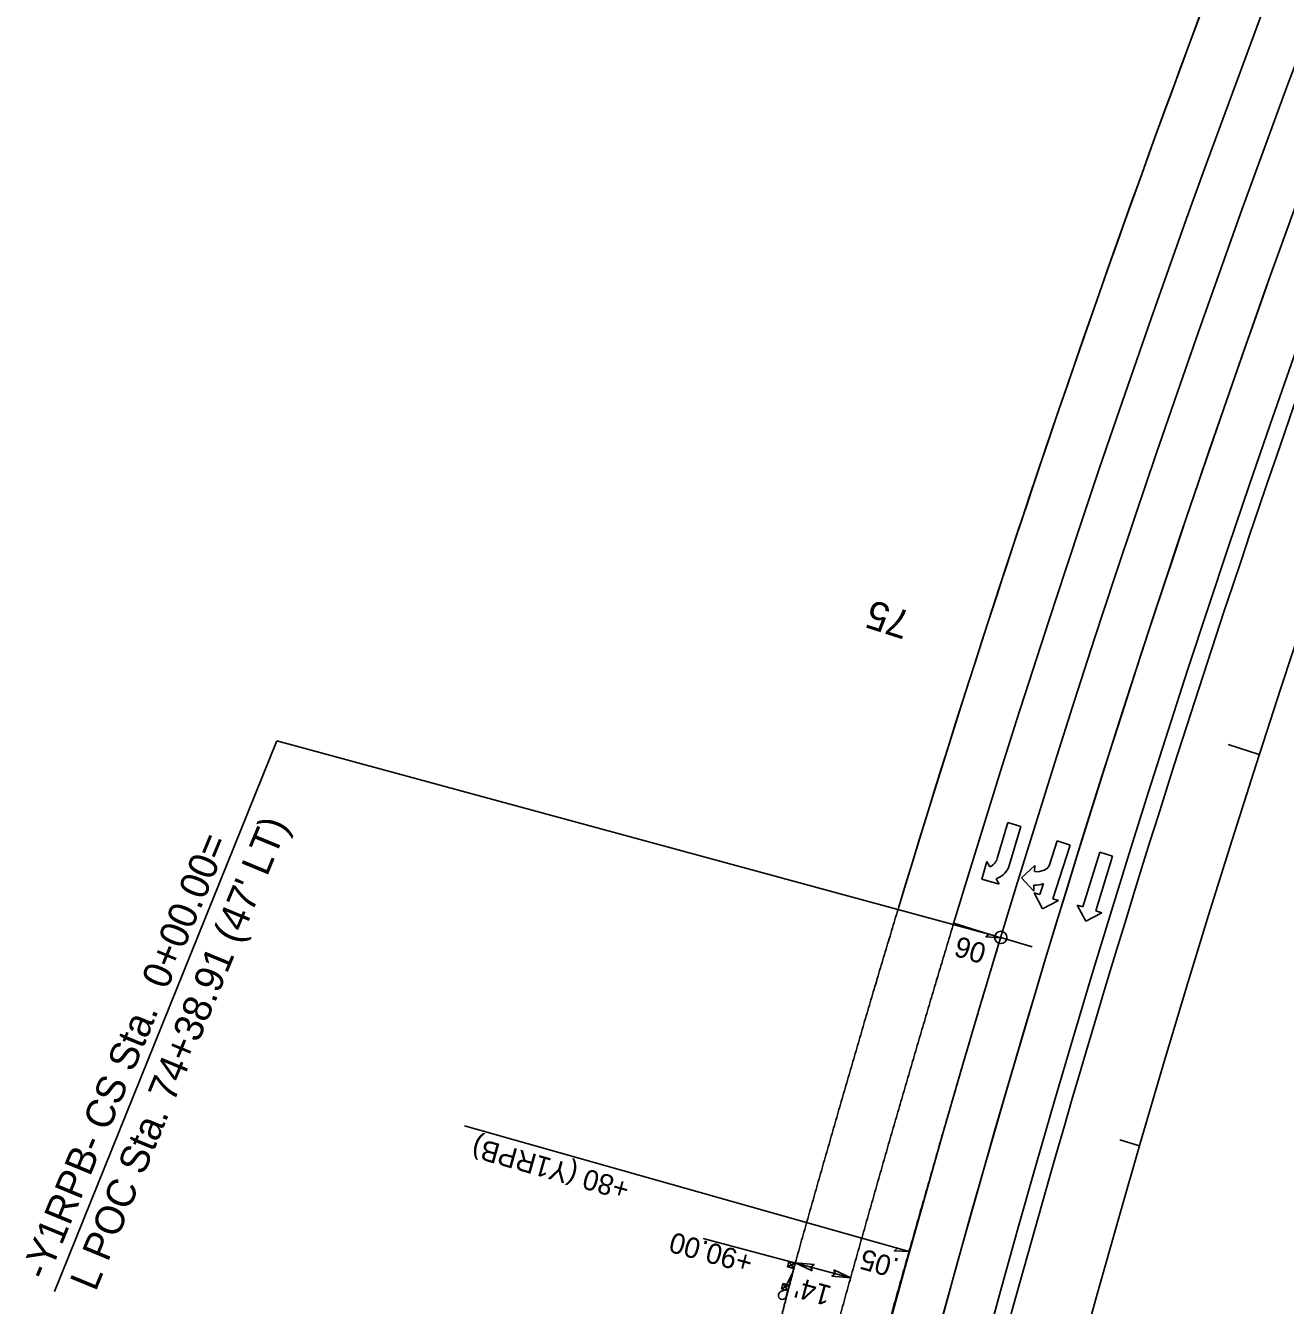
# Model space of a CAD drawing. Extents: x 2389694 to 2405615, y 547005 to 573532.
# Drawn here: x 2395096.3 to 2395404.2, y 556416.9 to 556729.7 of the extents above; entities that cross this region are included whole.
import ezdxf

# ---------------------------------------------------------------- set-up
doc = ezdxf.new("R2010")
doc.units = 0
for name, color, linetype in [('Old_Level_1', 7, 'Continuous'), ('Old_Level_22', 7, 'Continuous'), ('Prop Dimension', 7, 'Continuous'), ('Prop Dimension Text', 7, 'Continuous'), ('Prop EOT', 7, 'Continuous'), ('Prop GRAU CAT1 CELL', 7, 'Continuous'), ('Prop Guardrail', 7, 'Continuous'), ('Prop Horizontal Alignment', 7, 'Continuous'), ('Prop Horizontal Alignment Curve and Spiral Data', 7, 'Continuous'), ('Prop Horizontal Alignment Tick Large', 7, 'Continuous'), ('Prop Horizontal Alignment Tick Small', 7, 'Continuous'), ('Prop Lane Arrow Shared Rt and Thru CELL', 7, 'Continuous'), ('Prop Lane Arrow Through CELL', 7, 'Continuous'), ('Prop Lane Lines', 7, 'Continuous'), ('Prop Super Arrow 1 Lane CELL', 7, 'Continuous'), ('Prop Superelevation Label', 7, 'Continuous')]:
    doc.layers.add(name, color=color, linetype=linetype)

# ---------------------------------------------------------------- blocks, each defined once
blk = doc.blocks.new('CAT1 GRAU')
at = {"layer": 'Prop GRAU CAT1 CELL'}
for p, q in [((-0.02, -0.02), (6.71, -0.02)), ((-0.02, -0.02), (1.38, -0.02)), ((-0.02, -1.63), (-0.02, -0.02)), ((-0.02, -0.02), (1.38, -1.63)), ((1.38, -0.02), (-0.02, -1.63)), ((1.38, -1.63), (-0.02, -1.63)), ((1.38, -0.02), (1.38, -1.63)), ((6.27, -0.83), (2.47, -0.02)), ((5.57, -0.02), (6.97, -0.02)), ((5.57, -1.63), (5.57, -0.02)), ((5.57, -0.02), (6.97, -1.63)), ((6.97, -0.02), (5.57, -1.63)), ((6.97, -1.63), (5.57, -1.63)), ((6.71, -0.02), (6.44, -0.02)), ((6.71, -0.02), (8.42, -0.02)), ((6.97, -0.02), (6.97, -1.63)), ((7.63, -1.6), (6.97, -0.72))]:
    blk.add_line(p, q, dxfattribs=at)
blk.add_ellipse((8.42, -1.01), major_axis=(0, 0.993), ratio=0.995379, start_param=2.210226, end_param=6.283185, dxfattribs=at)

msp = doc.modelspace()

# ---------------------------------------------------------------- linework, layer by layer
at = {"layer": 'Prop Dimension'}
for p, q in [((2395300.65, 556433.28), (2395203.53, 556460.73)), ((2395297.94, 556423.62), (2395261.86, 556433.2))]:
    msp.add_line(p, q, dxfattribs=at)
for points in [[(2395288.55, 556425.32), (2395284.4, 556427.22), (2395288.98, 556426.83), (2395288.21, 556426.21)], [(2395293.78, 556425.53), (2395297.94, 556423.62), (2395293.36, 556424.01), (2395294.12, 556424.64)]]:
    msp.add_lwpolyline(points, close=True, dxfattribs=at)
at = {"layer": 'Prop EOT'}
for radius, start, end in [(3559, 136.54853, 163.17888), (3523, 136.54853, 169.40696), (3573, 151.19964, 163.17888), (3519, 155.66284, 169.40696)]:
    msp.add_arc((2398729.82, 555480.32), radius, start, end, dxfattribs=at)
for points in [[(2395309.71, 556514.32), (2395308.92, 556511.73), (2395308.14, 556509.12), (2395307.36, 556506.51), (2395306.57, 556503.91), (2395305.8, 556501.3), (2395305.02, 556498.69), (2395304.24, 556496.08), (2395303.47, 556493.48), (2395302.7, 556490.87), (2395301.93, 556488.26), (2395301.16, 556485.65), (2395300.4, 556483.04), (2395299.63, 556480.43), (2395298.87, 556477.82), (2395298.11, 556475.21), (2395297.35, 556472.6), (2395296.59, 556469.99), (2395295.84, 556467.38), (2395295.08, 556464.77), (2395294.33, 556462.16), (2395293.58, 556459.55), (2395292.83, 556456.94), (2395292.08, 556454.32), (2395291.33, 556451.71), (2395290.59, 556449.1), (2395289.84, 556446.49), (2395289.1, 556443.88), (2395288.36, 556441.26), (2395287.62, 556438.65), (2395286.88, 556436.04), (2395286.14, 556433.43), (2395285.41, 556430.81), (2395284.67, 556428.2), (2395284.38, 556427.17)], [(2395268.75, 556317.47), (2395269.46, 556320.07), (2395270.17, 556322.68), (2395270.88, 556325.29), (2395271.58, 556327.9), (2395272.29, 556330.51), (2395273, 556333.12), (2395273.71, 556335.73), (2395274.42, 556338.34), (2395275.13, 556340.94), (2395275.84, 556343.55), (2395276.55, 556346.16), (2395277.27, 556348.77), (2395277.98, 556351.38), (2395278.69, 556353.99), (2395279.4, 556356.6), (2395280.11, 556359.21), (2395280.83, 556361.82), (2395281.54, 556364.42), (2395282.25, 556367.03), (2395282.97, 556369.64), (2395283.68, 556372.25), (2395284.4, 556374.86), (2395285.12, 556377.47), (2395285.83, 556380.08), (2395286.55, 556382.69), (2395287.27, 556385.3), (2395287.99, 556387.9), (2395288.71, 556390.51), (2395289.43, 556393.12), (2395290.15, 556395.73), (2395290.87, 556398.34), (2395291.6, 556400.95), (2395292.32, 556403.55), (2395293.05, 556406.16), (2395293.77, 556408.77), (2395294.5, 556411.38), (2395295.23, 556413.99), (2395295.96, 556416.59), (2395296.69, 556419.2), (2395297.42, 556421.81), (2395298.15, 556424.41), (2395298.88, 556427.02), (2395299.62, 556429.63), (2395300.35, 556432.23), (2395301.09, 556434.84), (2395301.83, 556437.45), (2395302.57, 556440.05), (2395303.31, 556442.66), (2395304.05, 556445.26), (2395304.79, 556447.87), (2395305.54, 556450.47), (2395306.29, 556453.07), (2395307.03, 556455.68), (2395307.78, 556458.28), (2395308.53, 556460.89), (2395309.29, 556463.49), (2395310.04, 556466.09), (2395310.79, 556468.69), (2395311.55, 556471.3), (2395312.31, 556473.9), (2395313.07, 556476.5), (2395313.83, 556479.1), (2395314.59, 556481.7), (2395315.36, 556484.3), (2395316.13, 556486.9), (2395316.9, 556489.5), (2395317.67, 556492.1), (2395318.44, 556494.7), (2395319.21, 556497.3), (2395319.99, 556499.89), (2395320.77, 556502.49), (2395321.55, 556505.09), (2395322.33, 556507.69), (2395323.11, 556510.28)], [(2395284.4, 556427.22), (2395284.15, 556426.27), (2395283.91, 556425.34), (2395283.66, 556424.4), (2395283.42, 556423.46), (2395283.18, 556422.52), (2395282.94, 556421.59), (2395282.69, 556420.65), (2395282.45, 556419.71), (2395282.21, 556418.77), (2395281.97, 556417.84), (2395281.72, 556416.89), (2395281.48, 556415.96), (2395281.24, 556415.02), (2395281, 556414.08), (2395280.76, 556413.14), (2395280.52, 556412.21), (2395280.28, 556411.27), (2395280.04, 556410.33), (2395279.79, 556409.39), (2395279.55, 556408.45), (2395279.31, 556407.51), (2395279.07, 556406.57), (2395278.83, 556405.64), (2395278.59, 556404.69), (2395278.35, 556403.76), (2395278.11, 556402.82), (2395277.87, 556401.89), (2395277.63, 556400.94), (2395277.39, 556400.01), (2395277.15, 556399.07), (2395276.91, 556398.13), (2395276.67, 556397.19), (2395276.43, 556396.26), (2395276.19, 556395.32), (2395275.95, 556394.38), (2395275.71, 556393.44), (2395275.48, 556392.51), (2395275.24, 556391.56), (2395275, 556390.63), (2395274.76, 556389.69), (2395274.52, 556388.75), (2395274.28, 556387.81), (2395274.04, 556386.87), (2395273.81, 556385.94), (2395273.57, 556385), (2395273.33, 556384.06), (2395273.09, 556383.12), (2395272.86, 556382.19), (2395272.62, 556381.24), (2395272.38, 556380.31), (2395272.14, 556379.37), (2395271.9, 556378.44), (2395271.67, 556377.49), (2395271.43, 556376.56), (2395271.19, 556375.62), (2395270.96, 556374.69), (2395270.72, 556373.74), (2395270.48, 556372.81), (2395270.24, 556371.87), (2395270.01, 556370.93), (2395269.77, 556369.99), (2395269.53, 556369.05), (2395269.3, 556368.12), (2395269.06, 556367.18), (2395268.82, 556366.24), (2395268.59, 556365.3), (2395268.35, 556364.37), (2395268.11, 556363.43), (2395267.88, 556362.49), (2395267.64, 556361.55), (2395267.41, 556360.62), (2395267.17, 556359.68), (2395266.94, 556358.74), (2395266.7, 556357.8)]]:
    msp.add_spline(points, degree=3, dxfattribs=at)
at = {"layer": 'Prop Guardrail'}
msp.add_arc((2398729.82, 555480.32), 3573, 151.45837, 163.17888, dxfattribs=at)
msp.add_spline([(2395309.71, 556514.32), (2395308.92, 556511.73), (2395308.14, 556509.12), (2395307.36, 556506.51), (2395306.57, 556503.91), (2395305.8, 556501.3), (2395305.02, 556498.69), (2395304.24, 556496.08), (2395303.47, 556493.48), (2395302.7, 556490.87), (2395301.93, 556488.26), (2395301.16, 556485.65), (2395300.4, 556483.04), (2395299.63, 556480.43), (2395298.87, 556477.82), (2395298.11, 556475.21), (2395297.35, 556472.6), (2395296.59, 556469.99), (2395295.84, 556467.38), (2395295.08, 556464.77), (2395294.33, 556462.16), (2395293.58, 556459.55), (2395292.83, 556456.94), (2395292.08, 556454.32), (2395291.33, 556451.71), (2395290.59, 556449.1), (2395289.84, 556446.49), (2395289.1, 556443.88), (2395288.36, 556441.26), (2395287.62, 556438.65), (2395286.88, 556436.04), (2395286.14, 556433.43), (2395285.41, 556430.81), (2395284.67, 556428.2), (2395284.39, 556427.2)], degree=3, dxfattribs=at)
at = {"layer": 'Prop Horizontal Alignment'}
msp.add_arc((2398729.82, 555480.32), 3500, 136.54853, 177.15578, dxfattribs=at)
msp.add_spline([(2395280.33, 556314.32), (2395281.04, 556316.93), (2395281.75, 556319.54), (2395282.46, 556322.14), (2395283.16, 556324.75), (2395283.87, 556327.36), (2395284.58, 556329.97), (2395285.29, 556332.58), (2395286, 556335.18), (2395286.71, 556337.79), (2395287.42, 556340.4), (2395288.13, 556343.01), (2395288.84, 556345.61), (2395289.55, 556348.22), (2395290.27, 556350.83), (2395290.98, 556353.44), (2395291.69, 556356.04), (2395292.4, 556358.65), (2395293.12, 556361.26), (2395293.83, 556363.86), (2395294.54, 556366.47), (2395295.26, 556369.08), (2395295.97, 556371.68), (2395296.69, 556374.29), (2395297.4, 556376.9), (2395298.12, 556379.5), (2395298.84, 556382.11), (2395299.56, 556384.71), (2395300.28, 556387.32), (2395301, 556389.92), (2395301.72, 556392.53), (2395302.44, 556395.13), (2395303.16, 556397.74), (2395303.88, 556400.34), (2395304.61, 556402.95), (2395305.33, 556405.55), (2395306.06, 556408.15), (2395306.78, 556410.76), (2395307.51, 556413.36), (2395308.24, 556415.96), (2395308.97, 556418.56), (2395309.7, 556421.17), (2395310.43, 556423.77), (2395311.17, 556426.37), (2395311.9, 556428.97), (2395312.64, 556431.57), (2395313.37, 556434.17), (2395314.11, 556436.77), (2395314.85, 556439.37), (2395315.59, 556441.97), (2395316.33, 556444.57), (2395317.08, 556447.17), (2395317.82, 556449.77), (2395318.57, 556452.36), (2395319.31, 556454.96), (2395320.06, 556457.56), (2395320.81, 556460.15), (2395321.56, 556462.75), (2395322.32, 556465.35), (2395323.07, 556467.94), (2395323.83, 556470.54), (2395324.59, 556473.13), (2395325.35, 556475.72), (2395326.11, 556478.32), (2395326.87, 556480.91), (2395327.63, 556483.5), (2395328.4, 556486.09), (2395329.17, 556488.69), (2395329.94, 556491.28), (2395330.71, 556493.87), (2395331.48, 556496.46), (2395332.26, 556499.04), (2395333.04, 556501.63), (2395333.82, 556504.22), (2395334.6, 556506.81)], degree=3, dxfattribs=at)
at = {"layer": 'Prop Horizontal Alignment Curve and Spiral Data'}
for p, q in [((2395157.71, 556554.89), (2395103.32, 556420.26)), ((2395333.15, 556507.2), (2395157.71, 556554.89))]:
    msp.add_line(p, q, dxfattribs=at)
msp.add_circle((2395334.6, 556506.81), 1.5, dxfattribs=at)
at = {"layer": 'Prop Horizontal Alignment Tick Large'}
for p, q in [((2395397.77, 556551.52), (2395390.16, 556553.97)), ((2395334.6, 556506.81), (2395342.26, 556504.49))]:
    msp.add_line(p, q, dxfattribs=at)
at = {"layer": 'Prop Horizontal Alignment Tick Small'}
msp.add_line((2395368.53, 556455.9), (2395363.73, 556457.29), dxfattribs=at)
at = {"layer": 'Prop Lane Arrow Shared Rt and Thru CELL'}
for p, q in [((2395346.45, 556524.28), (2395348.43, 556530.42)), ((2395348.43, 556530.42), (2395351.57, 556529.41)), ((2395351.57, 556529.41), (2395347.34, 556516.28)), ((2395339.68, 556521.37), (2395342.95, 556524.36)), ((2395342.95, 556524.36), (2395342.9, 556522.9)), ((2395342.67, 556518.1), (2395339.68, 556521.37)), ((2395342.73, 556519.6), (2395342.67, 556518.1)), ((2395344.81, 556513.83), (2395342.77, 556517.75)), ((2395342.77, 556517.75), (2395344.19, 556517.29)), ((2395344.19, 556517.29), (2395345.07, 556520)), ((2395348.76, 556515.82), (2395344.81, 556513.83)), ((2395347.34, 556516.28), (2395348.76, 556515.82))]:
    msp.add_line(p, q, dxfattribs=at)
for centre, radius, start, end in [((2395343.38, 556527.32), 4.43, 263.858, 294.7116), ((2395344.32, 556525.64), 2.52, 291.2215, 327.5335), ((2395343.22, 556524.02), 4.43, 263.7392, 294.6178)]:
    msp.add_arc(centre, radius, start, end, dxfattribs=at)
at = {"layer": 'Prop Lane Arrow Through CELL'}
for p, q in [((2395333.74, 556526.14), (2395336.35, 556534.91)), ((2395336.35, 556534.91), (2395339.51, 556533.97)), ((2395339.51, 556533.97), (2395336.5, 556523.86)), ((2395354.71, 556514.26), (2395358.79, 556527.65)), ((2395361.95, 556526.69), (2395357.86, 556513.3)), ((2395358.79, 556527.65), (2395361.95, 556526.69)), ((2395329.97, 556521.06), (2395331.21, 556525.38)), ((2395331.21, 556525.38), (2395331.92, 556524.08)), ((2395334.21, 556519.85), (2395329.97, 556521.06)), ((2395333.5, 556521.15), (2395334.21, 556519.85)), ((2395355.41, 556510.75), (2395353.27, 556514.7)), ((2395353.27, 556514.7), (2395354.71, 556514.26)), ((2395359.3, 556512.86), (2395355.41, 556510.75)), ((2395357.86, 556513.3), (2395359.3, 556512.86))]:
    msp.add_line(p, q, dxfattribs=at)
for centre, radius, start, end in [((2395330.61, 556527.07), 3.27, 293.7308, 343.389), ((2395331.76, 556526.1), 5.25, 289.4012, 334.7129)]:
    msp.add_arc(centre, radius, start, end, dxfattribs=at)
at = {"layer": 'Prop Lane Lines'}
for radius, start in [(3547, 136.54853), (3535, 136.54853), (3535, 160.3873)]:
    msp.add_arc((2398729.82, 555480.32), radius, start, 169.40696, dxfattribs=at)
at = {"layer": 'Prop Super Arrow 1 Lane CELL'}
for p, q in [((2395334.57, 556506.72), (2395323.11, 556510.28)), ((2395312.2, 556430.01), (2395300.65, 556433.28))]:
    msp.add_line(p, q, dxfattribs=at)
for points in [[(2395334.57, 556506.72), (2395330.99, 556506.99), (2395331.75, 556507.59)], [(2395312.2, 556430.01), (2395308.61, 556430.19), (2395309.36, 556430.81)]]:
    msp.add_lwpolyline(points, close=True, dxfattribs=at)

# ---------------------------------------------------------------- block references
at = {"layer": 'Old_Level_1', "xscale": 0.99999907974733, "yscale": 0.9999990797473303, "rotation": -104.94064584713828}
msp.add_blockref('CAT1 GRAU', (2395284.39, 556427.18), dxfattribs=at)

# ---------------------------------------------------------------- texts
at = {"layer": 'Old_Level_22'}
for s, p in [("L POC Sta. 74+38.91 (47' LT)", (2395113.4, 556420.05)), ('-Y1RPB- CS Sta.  0+00.00=', (2395101.5, 556422.67))]:
    msp.add_text(s, height=7, rotation=67.5679, dxfattribs=at).set_placement(p)
at = {"layer": 'Prop Dimension Text'}
for s, rotation, p in [('+80 (Y1RPB)', 164.212, (2395244.27, 556447.27)), ('+90.00', 164.5605, (2395274.4, 556429.36)), ("14'", 164.5605, (2395293.57, 556421.45))]:
    msp.add_text(s, height=5, rotation=rotation, dxfattribs=at).set_placement(p)
at = {"layer": 'Prop Horizontal Alignment Curve and Spiral Data'}
msp.add_text('75', height=7, rotation=162.1782, dxfattribs=at).set_placement((2395313.06, 556586.26))
at = {"layer": 'Prop Superelevation Label'}
for s, rotation, p in [('06', 163.1782, (2395331.44, 556505.05)), ('.05', 164.212, (2395310.08, 556428.19))]:
    msp.add_text(s, height=5, rotation=rotation, dxfattribs=at).set_placement(p)

doc.saveas('drawing.dxf')
